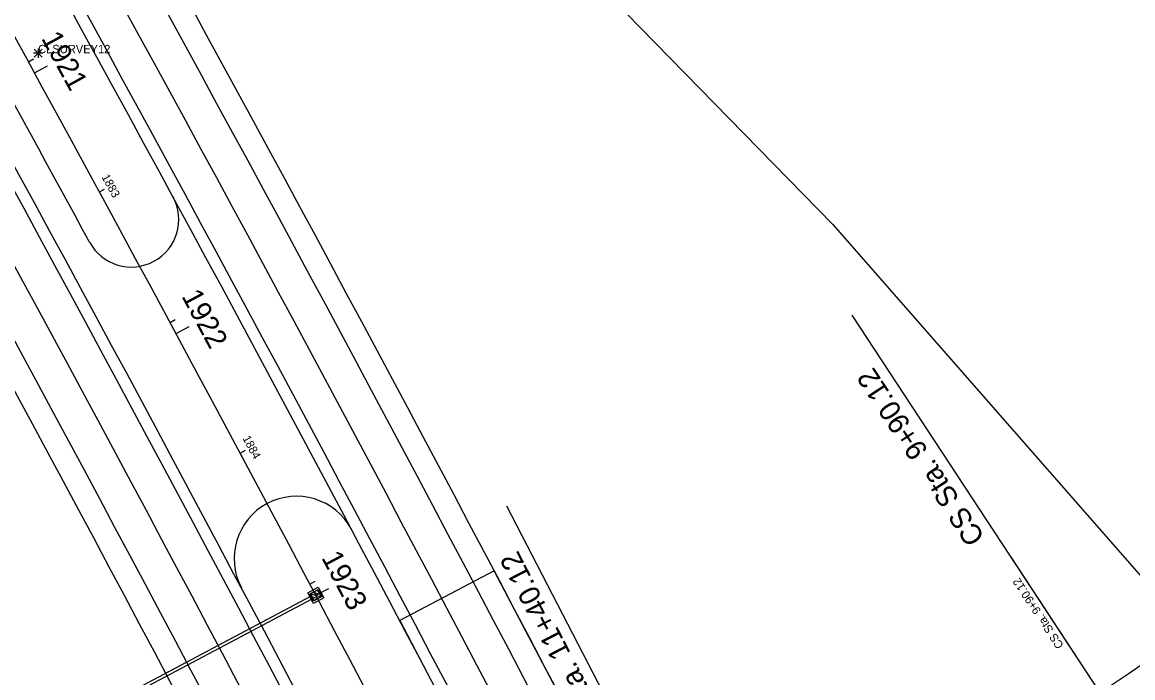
# Model space of a CAD drawing. Extents: x 6334 to 41599, y 9030 to 59113.
# Drawn here: x 24129.9 to 24504.1, y 28538.5 to 28759.5 of the extents above; entities that cross this region are included whole.
import ezdxf

# ---------------------------------------------------------------- set-up
doc = ezdxf.new("R2010")
doc.units = 0
for name, color, linetype in [('DR_X_Cells', 7, 'Continuous'), ('DR_X_Culvert', 7, 'Continuous'), ('GE_X_CL_20', 7, 'Continuous'), ('GE_X_CL_50', 7, 'Continuous'), ('GK_Drainage_Nodes', 7, 'Continuous'), ('GK_Visualization', 7, 'Continuous'), ('MT_P_Edge_Line', 7, 'Continuous'), ('PM_X_Lane_Line', 7, 'Continuous'), ('PV_X_EOP', 7, 'Continuous'), ('PV_X_Shoulder', 7, 'Continuous'), ('RW_X_Esmt_LA', 7, 'Continuous')]:
    doc.layers.add(name, color=color, linetype=linetype)

msp = doc.modelspace()

# ---------------------------------------------------------------- linework, layer by layer
at = {"layer": 'DR_X_Cells'}
for p, q in [((24227, 28566.87), (24230.6, 28565.76)), ((24228, 28567.4), (24230.48, 28566.64)), ((24229, 28567.93), (24229.95, 28567.64)), ((24227.17, 28565.98), (24229.6, 28565.23)), ((24227.7, 28564.98), (24228.6, 28564.7))]:
    msp.add_line(p, q, dxfattribs=at)
for points in [[(24229.65, 28569.03), (24231.52, 28565.5), (24227.99, 28563.62), (24226.12, 28567.16)], [(24229.62, 28568.26), (24230.87, 28565.9), (24228.02, 28564.39), (24226.77, 28566.75)], [(24229.37, 28568.13), (24230.62, 28565.77), (24228.26, 28564.53), (24227.02, 28566.88)]]:
    msp.add_lwpolyline(points, close=True, dxfattribs=at)
at = {"layer": 'DR_X_Culvert'}
for p, q in [((24156.12, 28528.4), (24227.16, 28566.01)), ((24156.58, 28527.52), (24227.63, 28565.13))]:
    msp.add_line(p, q, dxfattribs=at)
at = {"layer": 'GE_X_CL_20'}
for p, q in [((24131.95, 28746.17), (24133.7, 28747.13)), ((24155.9, 28702.28), (24157.65, 28703.23)), ((24179.69, 28658.3), (24181.45, 28659.25)), ((24203.33, 28614.24), (24205.1, 28615.19)), ((24498.05, 28526), (24462.96, 28579.38)), ((24226.82, 28570.1), (24228.59, 28571.04))]:
    msp.add_line(p, q, dxfattribs=at)
for centre, radius, start, end in [((11569.81, 21863.73), 14323.94, 27.320833, 30.120833), ((24105.17, 29123.62), 716.2, 303.32083, 318.10417)]:
    msp.add_arc(centre, radius, start, end, dxfattribs=at)
at = {"layer": 'GE_X_CL_50'}
for p, q in [((24134, 28742.42), (24138.39, 28744.82)), ((24497.22, 28527.25), (24409.49, 28660.7)), ((24181.72, 28654.54), (24186.12, 28656.91)), ((24366.73, 28453.96), (24293.18, 28596.34)), ((24228.82, 28566.33), (24233.24, 28568.67))]:
    msp.add_line(p, q, dxfattribs=at)
for centre, radius, start, end in [((11569.81, 21863.73), 14323.94, 27.320833, 30.120833), ((24105.17, 29123.62), 716.2, 303.32083, 318.10417)]:
    msp.add_arc(centre, radius, start, end, dxfattribs=at)
at = {"layer": 'GK_Drainage_Nodes'}
for p, q in [((24228.19, 28567.51), (24228.19, 28567.51)), ((24230, 28566.95), (24230, 28566.95)), ((24230.59, 28567.26), (24230.59, 28567.26)), ((24227.05, 28565.39), (24227.05, 28565.39)), ((24227.39, 28565.57), (24227.39, 28565.57)), ((24227.64, 28565.7), (24227.64, 28565.7)), ((24228.82, 28566.33), (24228.82, 28566.33)), ((24228.82, 28566.33), (24228.82, 28566.33)), ((24229.44, 28565.15), (24229.44, 28565.15))]:
    msp.add_line(p, q, dxfattribs=at)
at = {"layer": 'GK_Visualization'}
for p, q in [((24133.92, 28747.71), (24136.58, 28750.38)), ((24133.92, 28750.38), (24136.58, 28747.71)), ((24135.25, 28750.61), (24135.25, 28747.49)), ((24136.81, 28749.05), (24133.69, 28749.05))]:
    msp.add_line(p, q, dxfattribs=at)
for centre, radius, start, end in [((11569.81, 21863.73), 14323.94, 27.320833, 30.120833), ((11569.81, 21863.73), 14323.94, 27.320833, 30.120833), ((11569.81, 21863.73), 14323.94, 27.320833, 30.120833), ((24105.17, 29123.62), 716.2, 303.32083, 318.10417), ((24105.17, 29123.62), 716.2, 303.32083, 318.10417)]:
    msp.add_arc(centre, radius, start, end, dxfattribs=at)
at = {"layer": 'MT_P_Edge_Line'}
for p, q in [((24288.92, 28574.6), (24257.08, 28557.8)), ((24323.88, 28507.91), (24288.92, 28574.6)), ((24257.08, 28557.8), (24291.95, 28491.28))]:
    msp.add_line(p, q, dxfattribs=at)
at = {"layer": 'PM_X_Lane_Line'}
for radius in [14360.94, 14286.94]:
    msp.add_arc((11569.81, 21863.73), radius, 27.320833, 30.120833, dxfattribs=at)
at = {"layer": 'PV_X_EOP'}
for centre, radius, start, end in [((11569.81, 21863.73), 14372.94, 27.320833, 30.120833), ((11569.81, 21863.73), 14348.94, 27.320833, 30.120833), ((11569.81, 21863.73), 14298.94, 27.320833, 30.120833), ((11569.81, 21863.73), 14274.94, 27.320833, 30.120833), ((24105.17, 29123.62), 706.2, 303.32083, 318.10417)]:
    msp.add_arc(centre, radius, start, end, dxfattribs=at)
at = {"layer": 'PV_X_Shoulder'}
for centre, radius, start, end in [((11569.81, 21863.73), 14380.94, 27.320833, 30.120833), ((11569.81, 21863.73), 14344.94, 27.320833, 30.120833), ((11569.81, 21863.73), 14302.94, 27.320833, 30.120833), ((11569.81, 21863.73), 14266.94, 27.320833, 30.120833), ((11569.81, 21863.73), 14312.94, 28.464008, 29.11967), ((24166.63, 28692.98), 16, 208.4, 28.4), ((24222.28, 28578.7), 21, 28.04, 208.04)]:
    msp.add_arc(centre, radius, start, end, dxfattribs=at)
at = {"layer": 'RW_X_Esmt_LA'}
for p, q in [((24303.2, 28793.52), (24403.06, 28691.31)), ((24403.06, 28691.31), (24536.48, 28538.84))]:
    msp.add_line(p, q, dxfattribs=at)

# ---------------------------------------------------------------- texts
at = {"layer": 'GE_X_CL_20'}
for s, rotation, p in [('1883', 298.5171, (24156.54, 28707.37)), ('1884', 298.1171, (24204.04, 28619.29)), ('CS Sta. 9+90.12', 123.3208, (24480.95, 28549.46))]:
    msp.add_text(s, height=2.8, rotation=rotation, dxfattribs=at).set_placement(p)
at = {"layer": 'GE_X_CL_50'}
for s, rotation, p in [('1921', 298.7, (24136.18, 28754.07)), ('1922', 298.3, (24183.42, 28667.19)), ('CS Sta. 9+90.12', 123.3208, (24454.47, 28585.91)), ('1923', 297.9, (24230.57, 28579.04)), ('ST Sta. 11+40.12', 117.3208, (24330.34, 28516.77))]:
    msp.add_text(s, height=7, rotation=rotation, dxfattribs=at).set_placement(p)
at = {"layer": 'GK_Visualization'}
msp.add_text('CLSURVEY12', height=2.8, dxfattribs=at).set_placement((24135.25, 28749.05))

doc.saveas('drawing.dxf')
